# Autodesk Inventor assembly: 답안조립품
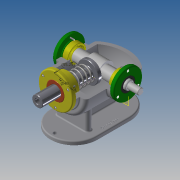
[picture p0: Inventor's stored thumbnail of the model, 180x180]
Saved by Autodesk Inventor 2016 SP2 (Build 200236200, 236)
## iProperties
Created: 2019-03
Part Number: 답안조립품
Document SubType Name: Assembly
Designer: EZ
Mass: 7822.92 g
Surface Area: 4109.01 cm^2
Volume: 1898.78 cm^3
Density: 4.11996 g/cm^3
Author: EZ
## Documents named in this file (14)
- X:\390307V1006 황수연\390307V1006-답안파일\답안조립품.iam
- X:\390307V1006 황수연\본체.ipt
- X:\390307V1006 황수연\베어링 6205.ipt
- X:\390307V1006 황수연\본체커버.ipt
- X:\390307V1006 황수연\볼트 M4.ipt
- X:\390307V1006 황수연\부시.ipt
- X:\390307V1006 황수연\상부 캡.ipt
- X:\390307V1006 황수연\슬라이드 커버.ipt
- X:\390307V1006 황수연\슬라이드.ipt
- X:\390307V1006 황수연\오일 실.ipt
- X:\390307V1006 황수연\축 커버-1.ipt
- X:\390307V1006 황수연\축 커버-2.ipt
- X:\390307V1006 황수연\편심축.ipt
- X:\390307V1006 황수연\390307V1006-답안파일\가변스프링.ipt
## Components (1 placed, 1 different names)
1. 가변스프링:1
